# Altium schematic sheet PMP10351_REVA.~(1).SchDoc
size 431 x 279 mm; Date: Not shown in title block; ApprovedBy: Not shown in title block; CheckedBy: Not shown in title block; Author: Not shown in title block; CompanyName: Not shown in title block; Engineer: Not shown in title block; Organization: Not shown in title block; Address1: Not shown in title block; Address2: Not shown in title block; Address3: Not shown in title block; Address4: Not shown in title block; DocumentNumber: 1; Revision: Use project parameter SCH_Rev; SheetNumber: 1; SheetTotal: 1; PageSetup: Record=PageOptions|CenterHorizontal=True|CenterVertical=True|PrintScale=1.00|XCorrection=1.00|YCorrection=1.00|PrintKind=0|BorderSize=5000000|LeftOffset=0|BottomOffset=0|Orientation=2|PaperLength=1000|PaperWidth=1000|Scale=100|PaperSource=15|PrintQuality=600|MediaType=1|DitherType=10|PaperKind=Letter|PrintScaleMode=1
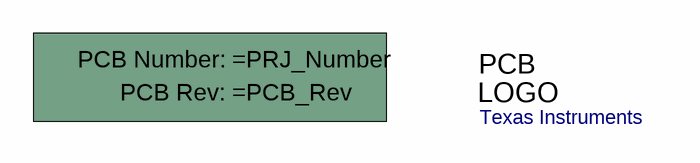
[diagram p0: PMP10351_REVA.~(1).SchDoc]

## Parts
!PCB  Printed Circuit Board  (value not drawn)  (mechanical)
Logo1  Texas Instruments  [TI_Stacked_SolderMask_Small]  (no BOM)

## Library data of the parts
!PCB = PCB: Manufacturer: Any; SymbolCreator: a0412235
Logo1 = TI_Logo: Texas Instrument Corporate Signature; SymbolCreator: a0412235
